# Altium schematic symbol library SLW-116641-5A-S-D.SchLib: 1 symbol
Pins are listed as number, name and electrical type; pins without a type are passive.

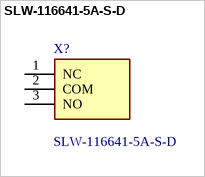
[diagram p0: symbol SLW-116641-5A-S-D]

## SLW-116641-5A-S-D
designator X?
SLW-116641-5A-S-D - 11.6 x 6 x 4.1 mm, 5 mm Raised Slide Actuator, Through Hole, Slide Switch; Manufacturer_Name: Same Sky; Geometry.Height: 11.3mm
footprint SLW1166415ASD
pins: 1 NC, 2 COM, 3 NO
